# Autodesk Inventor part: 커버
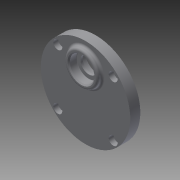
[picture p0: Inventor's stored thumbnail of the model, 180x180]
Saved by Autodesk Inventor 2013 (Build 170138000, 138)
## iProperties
Created: 2015-07
Part Number: 커버
Material: 일반
Document SubType Name: Modeling
Designer: user
Density: 1 g/cm^3
Author: user
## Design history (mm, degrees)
sketch "스케치1"
  geometry: C1 r 40 at (0, 0); 1 further point
  constraints: 1 centre point, 1 coincident
  dimensions: "d0" = 80 diameter of C1
extrude "돌출1" new body sketch "스케치1" distance "d1" = 9; taper "d2" = 0 deg
sketch "스케치2"
  geometry: L1 (0, 0)-(0, 11); L2 (0, 0)-(0, -20); C1 r 40 at (0, 0) reference; C2 r 14 at (0, 11); C3 r 14 at (0, -20)
  constraints: 4 end point, 2 centre point, 2 coincident, 1 collinear, 1 vertical
  dimensions: "d3" = 11 distance of L1.start L1.end; "d4" = 28 diameter of C2; "d5" = 20 distance of L1.start L2.end; "d6" = 28 diameter of C3
extrude "돌출2" join sketch "스케치2" distance "d7" = 3; taper "d8" = 0 deg
sketch "스케치3"
  geometry: L1 (0, 0)-(0, 20); C1 r 40 at (0, 0) reference; C2 r 15 at (0, 20)
  constraints: 2 end point, 1 centre point, 1 coincident, 1 vertical
  dimensions: "d9" = 20 distance of L1.start L1.end; "d10" = 30 diameter of C2
extrude "돌출3" join sketch "스케치3" distance "d11" = 4; taper "d12" = 0 deg
sketch "스케치4"
  geometry: C1 r 15 at (0, 0) reference; C2 r 11 at (0, 0); 1 further point
  constraints: 1 centre point, 1 coincident
  dimensions: "d13" = 22 diameter of C2
extrude "돌출4" cut sketch "스케치4" distance "d14" = 7; taper "d15" = 0 deg
sketch "스케치5"
  geometry: C1 r 11 at (0, 0) reference; C2 r 7.5 at (0, 0); 1 further point
  constraints: 1 centre point, 1 coincident
  dimensions: "d16" = 15 diameter of C2
extrude "돌출5" cut sketch "스케치5" distance "d17" = 2; taper "d18" = 0 deg
sketch "스케치6"
  geometry: C1 r 14 at (0, 0) reference; C2 r 11 at (0, 0); 1 further point
  constraints: 1 centre point, 1 coincident
  dimensions: "d19" = 22 diameter of C2
extrude "돌출6" cut sketch "스케치6" distance "d20" = 7; taper "d21" = 0 deg
sketch "스케치7"
  geometry: C1 r 14 at (0, 0) reference; C2 r 11 at (0, 0); 1 further point
  constraints: 1 centre point, 1 coincident
  dimensions: "d22" = 22 diameter of C2
extrude "돌출7" cut sketch "스케치7" distance "d23" = 7; taper "d24" = 0 deg
sketch "스케치8"
  geometry: C1 r 9 at (0, 0); 2 further points
  constraints: 1 centre point, 1 coincident, 1 vertical alignment
  dimensions: "d25" = 18 diameter of C1
extrude "돌출8" cut sketch "스케치8" distance "d26" = 1; taper "d27" = 0 deg
sketch "스케치9"
  geometry: L1 (0, 0)-(24.749, 24.749); L2 (0, 0)-(35, 0); C1 r 40 at (0, 0) reference; C2 r 4 at (24.749, 24.749); C3 r 4 at (-24.749, 24.749); C4 r 4 at (-24.749, -24.749); C5 r 4 at (24.749, -24.749); A1 r 35 centre (0, 0) between (24.749, 24.749) and (35, 0)
  constraints: 5 centre point, 4 end point, 2 coincident, 2 point on circle, 1 horizontal, 9 other
  dimensions: "d28" = 70 diameter of A1; "d29" = 45 deg angle of L2 L1; "d31" = 8 diameter of C2; "d34" = 360 deg dimension on C1.centre C2.centre (derived)
extrude "돌출9" cut sketch "스케치9" distance "d36" = 4.4; taper "d37" = 0 deg
sketch "스케치10"
  geometry: C1 r 4 at (0, 0) reference; C2 r 2.25 at (0, 0); 1 further point
  constraints: 1 centre point, 1 coincident
  dimensions: "d38" = 4.5 diameter of C2
extrude "돌출10" cut sketch "스케치10" distance "d39" = 10; taper "d40" = 0 deg
chamfer "모따기1" distance "d44" = 1; stored, may be unused: second distance "d45" = 2, angle "d46" = 45 deg
fillet "모깎기1" dims "d47" = 2
fillet "모깎기2" dims "d48" = 2
fillet "모깎기3" dims "d49" = 0.3
node "솔리드1"
pattern_circular "원형 패턴1" dims angle "d42" = 360 deg
